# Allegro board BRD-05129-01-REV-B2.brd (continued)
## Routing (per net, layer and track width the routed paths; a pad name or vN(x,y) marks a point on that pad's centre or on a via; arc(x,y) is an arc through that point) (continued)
MIO47: length 73.6
  TOP w0.13: JA1.C34 14.33,62.75 v4(14.35,62.75) ; v1(54,81.78) 55.29,83.07 R554.1 R543.2 55.92,88.42 56.2,88.14 59.07,88.14 60.19,89.26 U98.30
  L05_SIG w0.102: v4(14.35,62.75) 13.88,62.28 13.88,61.96 14.19,61.64 14.58,61.64 14.87,61.35 16.07,61.35 16.19,61.23 17.18,61.23 17.43,60.98 18.54,60.98 19.81,59.71 23.16,59.71 23.88,60.43 24.42,60.43 24.6,60.61 24.6,60.96 24.72,61.08 25.08,61.08 25.21,60.96 25.21,60.61 25.38,60.43 25.64,60.43 25.81,60.61 25.81,61.04 25.99,61.22 26.25,61.22 26.42,61.04 26.42,60.61 26.6,60.43 26.86,60.43 27.03,60.61 27.03,61.04 27.21,61.22 27.47,61.22 27.64,61.04 27.64,60.61 27.82,60.43 28.07,60.43 28.25,60.61 28.25,61.04 28.43,61.22 28.68,61.22 28.86,61.04 28.86,60.61 29.04,60.43 29.29,60.43 29.47,60.61 29.47,61.04 29.65,61.22 29.9,61.22 30.08,61.04 30.08,60.61 30.26,60.43 30.51,60.43 30.69,60.61 30.69,61.04 30.87,61.22 31.12,61.22 31.3,61.04 31.3,60.61 31.48,60.43 31.73,60.43 31.91,60.61 31.91,61.04 32.09,61.22 32.92,61.22 46.38,74.68 46.38,76.91 47.14,77.67 50.21,77.67 54,81.46 v1(54,81.78)
MIO48: length 91
  TOP w0.13: U98.29 60.25,89.76 58.95,88.46 56.38,88.46 55.93,88.91 v1(55.93,89.31) R542.2 R553.1 ; JA1.C35 v4(13.46,62.79)
  L05_SIG w0.102: v4(13.46,62.79) 13.88,63.2 13.88,66.82 14.43,67.37 17.1,67.37 17.41,67.67 17.95,67.67 18.1,67.82 18.1,68.38 18.25,68.52 18.46,68.52 18.61,68.38 18.61,67.82 18.76,67.67 18.97,67.67 19.12,67.82 19.12,68.38 19.27,68.52 19.48,68.52 19.63,68.38 19.63,67.82 19.77,67.67 19.98,67.67 20.13,67.82 20.13,68.38 20.28,68.52 20.49,68.52 20.64,68.38 20.64,67.82 20.79,67.67 21,67.67 21.15,67.82 21.15,68.38 21.3,68.52 21.51,68.52 21.66,68.38 21.66,67.82 21.81,67.67 22.87,67.67 36.29,81.1 36.29,81.73 37.51,82.95 38.67,82.95 39.39,83.67 39.39,84.78 39.82,85.21 40.41,85.21 40.84,85.65 41.05,85.65 42.41,84.3 42.62,84.3 42.77,84.45 42.77,84.66 41.41,86.01 41.41,86.22 41.56,86.37 41.77,86.37 43.12,85.02 43.33,85.02 43.48,85.16 43.48,85.37 42.13,86.73 42.13,86.94 42.28,87.09 42.49,87.09 43.84,85.73 44.05,85.73 44.2,85.88 44.2,86.09 42.85,87.45 42.85,87.66 46.02,90.83 51.14,90.83 51.28,90.68 51.28,87.88 51.43,87.73 51.64,87.73 51.79,87.88 51.79,88.17 51.94,88.32 52.55,88.32 52.7,88.47 52.7,88.68 52.55,88.83 51.94,88.83 51.79,88.98 51.79,90.68 51.94,90.83 54.41,90.83 v1(55.93,89.31)
MIO49: length 93.9
  TOP w0.13: JA1.C36 v4(14.29,63.99) ; U98.35 63.53,87.77 63.24,87.47 63.24,85.69 R552.1 62.55,84.66 62.8,84.66 62.92,84.54 62.92,82.99 62.49,82.55 62.31,82.55 R541.2 61.97,79.92 v1(61.59,79.55)
  L05_SIG w0.102: v4(14.29,63.99) 14.77,63.51 14.77,61.99 15.14,61.62 16.11,61.62 16.26,61.47 19.09,61.47 19.66,60.9 22.65,60.9 23.54,61.79 31.62,61.79 32.67,62.84 32.67,63.05 32.08,63.65 32.08,63.86 32.23,64 32.44,64 33.03,63.41 33.24,63.41 33.39,63.56 33.39,63.77 32.8,64.36 32.8,64.57 32.95,64.72 33.16,64.72 33.75,64.13 33.96,64.13 34.11,64.28 34.11,64.49 33.52,65.08 33.52,65.29 33.67,65.44 33.88,65.44 34.47,64.85 34.68,64.85 34.83,65 34.83,65.21 34.24,65.8 34.24,66.01 34.38,66.16 34.6,66.16 35.19,65.57 35.4,65.57 35.55,65.72 35.55,65.93 34.95,66.52 34.95,66.73 35.1,66.88 35.31,66.88 35.91,66.29 36.12,66.29 36.27,66.43 36.27,66.65 35.67,67.24 35.67,67.45 35.82,67.6 36.03,67.6 36.62,67 36.83,67 36.98,67.15 36.98,67.36 36.39,67.96 36.39,68.17 36.54,68.32 36.75,68.32 37.34,67.72 37.55,67.72 37.7,67.87 37.7,68.08 37.11,68.67 37.11,68.88 37.26,69.03 37.47,69.03 38.06,68.44 38.27,68.44 38.42,68.59 38.42,68.8 37.83,69.39 37.83,69.6 37.98,69.75 38.19,69.75 38.78,69.16 38.99,69.16 39.14,69.31 39.14,69.52 38.55,70.11 38.55,70.32 38.7,70.47 38.91,70.47 39.5,69.88 39.71,69.88 39.86,70.03 39.86,70.24 39.27,70.83 39.27,71.04 39.41,71.19 39.62,71.19 40.22,70.6 40.43,70.6 43.4,73.57 43.4,73.9 44.35,74.85 44.7,74.85 45.61,75.76 45.61,76.85 46.92,78.15 49.12,78.15 50.21,79.24 50.72,79.24 55.51,84.03 57.11,84.03 v1(61.59,79.55)
MIO50: length 87.9
  TOP w0.13: JA1.B36 v4(16.01,64.02) ; U98.23 60.18,92.76 59.82,93.12 59.82,93.62 58.7,94.75 56.22,94.75 v1(55.93,95.04)
  L05_SIG w0.102: v1(55.93,95.04) 61.89,95.04 63.45,93.48 66.05,93.48 66.51,93.02 66.51,89.35 66.09,88.93 65.3,88.93 65.15,89.08 65.15,89.57 65,89.72 64.79,89.72 64.65,89.57 64.65,89.08 64.5,88.93 64.29,88.93 64.14,89.08 64.14,89.57 63.99,89.72 63.78,89.72 63.63,89.57 63.63,89.08 63.48,88.93 63.27,88.93 63.12,89.08 63.12,89.57 62.97,89.72 62.76,89.72 62.61,89.57 62.61,89.08 62.46,88.93 59.92,88.93 59.52,88.54 56.6,88.54 56.35,88.29 54.79,88.29 49.31,82.81 47.18,82.81 46.72,83.27 40.53,83.27 39.24,81.98 37.91,81.98 37.26,81.33 37.26,80 36.39,79.13 36.39,79.13 23.86,66.6 18.21,66.6 16.46,64.85 16.46,64.47 v4(16.01,64.02)
MIO51: length 92.3
  TOP w0.13: R536.2 55.16,96.84 v1(55.16,96.29) 55.16,95.04 55.85,94.35 58.21,94.35 58.66,93.91 58.66,93.23 59.63,92.26 U98.24 ; JA1.B37 v4(15.19,64.08)
  L05_SIG w0.102: v4(15.19,64.08) 15.59,64.49 15.59,64.89 16.38,65.68 16.38,66.73 16.74,67.09 23.66,67.09 36.78,80.2 36.78,81.53 37.71,82.46 39.04,82.46 40.33,83.75 42.07,83.75 46.92,83.75 47.38,83.29 49.11,83.29 54.6,88.78 56.15,88.78 57.06,89.69 57.16,89.69 57.31,89.84 57.31,92.6 57.46,92.75 57.67,92.75 57.82,92.6 57.82,89.84 57.96,89.69 59.69,89.69 59.84,89.84 59.84,92.98 59.98,93.13 60.2,93.13 60.34,92.98 60.34,89.84 60.49,89.69 60.72,89.69 61.23,90.2 61.23,93.4 60.19,94.44 55.58,94.44 55.16,94.86 v1(55.16,96.29)
MIO52: length 34.9
  TOP w0.13: JA1.D36 v4(13.47,64.02)
  L03_SIG w0.102: v1(41.17,74.24) 29.36,62.43 17.93,62.43 17.42,62.94 17.42,62.95 17.19,63.18 15.46,63.18 15.36,63.27 14.06,63.27 13.47,63.87 v4(13.47,64.02)
  BOTTOM w0.13: U37.1 v1(41.17,74.24)
MIO53: length 38.8
  TOP w0.13: JA1.D37 v4(12.65,64.08)
  L03_SIG w0.102: v4(12.65,64.08) 13.29,63.44 13.56,63.44 13.86,63.13 13.86,62 13.92,61.94 13.92,61.94 14.13,61.72 14.14,61.72 14.16,61.7 17.23,61.7 17.37,61.83 19.6,61.83 20.53,60.9 23.01,60.9 23.94,61.83 31.1,61.83 41,71.74 v1(41,72.25)
  BOTTOM w0.13: v1(41,72.25) 41.2,72.25 42.37,73.42 U37.31
MIO54: length 37
  TOP w0.13: JA1.D38 v4(12.65,64.72)
  L03_SIG w0.102: v1(38.48,77.21) 37.9,77.8 36.93,77.8 29.64,70.51 14.42,70.51 13.89,69.98 13.89,67.59 13.09,66.79 13.09,65.17 v4(12.65,64.72)
  BOTTOM w0.13: v1(38.48,77.21) U37.5
MIO55: length 35.6
  TOP w0.13: JA1.C38 v4(13.46,64.69)
  L03_SIG w0.102: v4(13.46,64.69) 13.83,64.33 13.83,63.86 14.14,63.55 15.47,63.55 15.64,63.38 17.46,63.38 17.88,62.97 28.85,62.97 v1(38.76,72.87)
  BOTTOM w0.13: v1(38.76,72.87) 38.76,74.67 39.8,75.71 U37.2
MIO56: length 31.8
  TOP w0.13: JA1.C39 v4(14.29,65.9)
  L03_SIG w0.102: v1(38.48,76.21) 37.93,76.21 30.28,68.57 18.96,68.57 17.6,67.2 15.16,67.2 14.78,66.82 14.78,66.39 v4(14.29,65.9)
  BOTTOM w0.13: U37.3 v1(38.48,76.21)
MIO57: length 31.8
  TOP w0.13: JA1.C40 v4(14.29,66.53)
  L03_SIG w0.102: v1(39.29,76.71) 37.57,76.71 29.94,69.08 18.74,69.08 17.06,67.41 14.7,67.41 14.29,66.99 v4(14.29,66.53)
  BOTTOM w0.13: U37.4 v1(39.29,76.71)
MIO58: length 40.2
  TOP w0.13: JA1.B40 v4(15.19,65.99)
  L03_SIG w0.102: v1(42.34,71.73) 42.34,72.94 42.4,73.01 42.4,73.93 41.56,74.77 40.87,74.77 39.77,73.68 38.83,73.68 29.41,64.26 17.73,64.26 17.08,63.61 15.81,63.61 15.59,63.83 15.59,65.58 v4(15.19,65.99)
  BOTTOM w0.13: U37.29 43.37,73.73 43.36,73.72 43.36,73.49 43.09,73.21 42.98,73.21 42.34,72.57 v1(42.34,71.73)
MIO59: length 32.1
  TOP w0.13: JA1.B41 v4(15.19,66.62)
  L03_SIG w0.102: v1(39.67,77.71) 39.85,77.54 39.85,76.45 39.06,75.66 38.06,75.66 30.36,67.96 19.32,67.96 18.17,66.81 17.51,66.81 17.34,66.98 15.54,66.98 v4(15.19,66.62)
  BOTTOM w0.13: U37.6 v1(39.67,77.71)
MIO60: length 30.6
  TOP w0.13: JA1.B42 v4(16.01,67.83)
  L03_SIG w0.102: v4(16.01,67.83) 16.38,68.2 16.38,69.19 16.86,69.67 29.64,69.67 v1(37.18,77.21)
  BOTTOM w0.13: v1(37.18,77.21) 38.18,78.21 U37.7
MIO61: length 37
  TOP w0.13: JA1.A38 v4(16,64.69)
  L03_SIG w0.102: v1(40.84,80.18) 41.88,79.14 41.88,76.32 39.79,74.23 38.7,74.23 29.52,65.05 16.35,65.05 v4(16,64.69)
  BOTTOM w0.13: U37.9 41.87,79.61 41.3,80.18 v1(40.84,80.18)
MIO62: length 36.8
  TOP w0.13: JA1.A39 v4(16.83,65.9)
  L03_SIG w0.102: v7(41.83,80.36) 41.42,80.77 40.61,80.77 40.28,80.44 40.28,79.75 41.09,78.94 41.09,76.33 39.53,74.77 38.53,74.77 29.29,65.53 17.2,65.53 v4(16.83,65.9)
  BOTTOM w0.13: v7(41.83,80.36) 42.37,79.82 U37.10
MIO63: length 39.8
  TOP w0.13: JA1.A40 v4(16.83,66.53)
  L03_SIG w0.102: v1(43.76,80.31) 42.47,81.6 39.65,81.6 39.37,81.32 39.37,78.73 40.39,77.71 40.39,76.32 39.33,75.25 38.33,75.25 30.42,67.34 20.27,67.34 19.02,66.09 17.27,66.09 v4(16.83,66.53)
  BOTTOM w0.13: U37.13 43.87,80.2 v1(43.76,80.31)
MIO64_NC: length 0.4
  TOP w0.13: JA1.D40 v4(12.65,65.99)
MIO65_NC: length 0.4
  TOP w0.13: JA1.D41 v4(12.65,66.62)
MIO66: length 126.6
  TOP w0.13: U94.B4 U94.A4 107.02,103.54 106.51,104.05 v1(106.13,104.05) ; JA1.D42 v4(13.47,67.83)
  L05_SIG w0.102: v4(13.47,67.83) 13.06,68.24 13.06,68.72 11.91,69.88 11.91,72.36 12.65,73.1 23.99,73.1 30.77,79.88 30.77,81.75 31.12,82.1 31.12,84.59 35.81,89.28 39.58,89.28 42.22,91.91 42.22,92.11 44.55,94.43 46.68,94.43 48.61,96.36 48.61,97 49.37,97.76 51.79,97.76 54.3,100.27 62.85,100.27 63.72,101.15 78.03,101.15 86.31,109.43 104.74,109.43 106.74,107.43 106.74,104.66 v1(106.13,104.05)
MIO67: length 124.3
  TOP w0.13: JA1.C42 v4(14.29,67.8) ; v1(106,107.35) U94.A1 108.65,107.35 109.04,106.96 U94.B1
  L05_SIG w0.102: v4(14.29,67.8) 13.87,68.22 13.87,70.08 13.58,70.36 12.59,70.36 12.47,70.49 12.47,71.67 12.59,71.8 17.04,71.8 17.52,72.28 23.86,72.28 32.13,80.56 32.13,83.97 36.93,88.77 40.38,88.77 45.41,93.8 47.19,93.8 49.58,96.19 50.97,96.19 54.56,99.77 63.41,99.77 64.31,100.67 74.25,100.67 74.39,100.52 74.39,100.32 74.54,100.17 74.75,100.17 74.9,100.32 74.9,100.52 75.05,100.67 75.26,100.67 75.41,100.52 75.41,100.32 75.56,100.17 75.77,100.17 75.92,100.32 75.92,100.52 76.07,100.67 76.28,100.67 76.43,100.52 76.43,100.32 76.57,100.17 76.79,100.17 76.93,100.32 76.93,100.52 77.08,100.67 78.55,100.67 86.82,108.95 103.03,108.95 104.63,107.35 v1(106,107.35)
MIO68: length 130.3
  TOP w0.13: JA1.C43 v4(14.29,68.44) ; U94.B8 111.82,100.12 112.21,99.73 U94.A8 v1(114.69,99.73)
  L05_SIG w0.102: v1(114.69,99.73) 112.78,101.65 105.58,101.65 104.26,102.97 104.26,105.88 101.68,108.46 87.7,108.46 78.59,99.36 54.86,99.36 51.16,95.66 49.56,95.66 47.11,93.21 45.64,93.21 40.59,88.16 37.23,88.16 33.99,84.92 33.99,83.85 32.71,82.57 32.71,80.46 23.7,71.45 18.21,71.45 17.4,70.63 16.73,70.63 16.53,70.43 15.06,70.43 14.73,70.1 14.73,68.88 v4(14.29,68.44)
MIO69_NC: length 0.6
  TOP w0.13: JA1.C44 v4(13.46,68.5)
MIO70: length 125.9
  TOP w0.13: v1(116.09,89.69) 118.23,89.69 119.09,90.56 U95.4 ; JA1.B44 v4(15.19,68.53)
  L05_SIG w0.102: v1(116.09,89.69) 114.22,89.69 113.96,89.96 110.89,89.96 109.45,91.4 107.92,91.4 105.61,93.71 105,93.71 104.82,93.53 104.82,93.1 104.7,92.98 104.34,92.98 104.21,93.1 104.21,93.53 104.03,93.71 91.32,93.71 90.55,94.47 79.34,94.47 79.03,94.78 69.58,94.78 69.24,94.43 63.88,94.43 61.51,96.8 54.81,96.8 53.72,95.7 53.72,94.69 52.96,93.92 52.96,93.09 51.18,91.31 45.82,91.31 40.56,86.05 39.72,86.05 38.32,84.65 38.32,83.81 37.94,83.43 37.31,83.43 35.81,81.93 35.81,81.3 23.8,69.29 17.88,69.29 17.7,69.47 16.66,69.47 16.3,69.11 15.77,69.11 v4(15.19,68.53)
  BOTTOM w0.13: v1(116.09,89.69) 116.13,89.73 R683.2
MIO71: length 133.5
  TOP w0.13: R682.1 v1(121.88,94.46) 121.63,94.22 U95.2 ; JA1.B45 v4(16.01,69.73)
  L05_SIG w0.102: v1(121.88,94.46) 119.66,96.68 115.5,96.68 113.86,98.32 106.7,98.32 100.2,104.82 100.2,106.73 98.94,107.98 87.97,107.98 77.88,97.89 54.07,97.89 51.32,95.13 51.32,94.7 49.09,92.48 45.61,92.48 40.48,87.35 37.82,87.35 35.54,85.07 35.54,84.23 33.19,81.88 33.19,80.26 23.23,70.3 17.7,70.3 17.55,70.45 16.81,70.45 16.6,70.24 16.52,70.24 v4(16.01,69.73)
MIO72: length 127.2
  TOP w0.13: JA1.B46 v4(15.19,69.8) ; v1(116.06,90.85) 116.51,91.31 117.39,91.31 117.82,91.74 U95.5 117.82,93.82 118.03,94.02 120.2,94.02 120.36,93.86 U95.3
  L05_SIG w0.102: v1(116.06,90.85) 113.79,93.12 113.58,93.12 113.32,92.85 113.11,92.85 112.96,93 112.96,93.21 113.22,93.48 113.22,93.69 112.72,94.19 91.53,94.19 90.76,94.97 82.93,94.97 82.92,94.95 79.54,94.95 79.23,95.26 71.59,95.26 69.57,97.28 54.35,97.28 52.02,94.94 52.02,94 51.61,93.59 51.61,93.06 50.44,91.89 45.74,91.89 45.64,91.79 45.62,91.79 40.46,86.64 39.16,86.64 34.25,81.72 34.25,80.42 23.6,69.77 17.9,69.77 17.83,69.7 16.57,69.7 16.2,69.33 15.66,69.33 v4(15.19,69.8)
  BOTTOM w0.13: R681.1 115.8,90.59 v1(116.06,90.85)
MIO73_NC: length 0.4
  TOP w0.13: JA1.A42 v4(16.83,67.8)
MIO74_NC: length 0.4
  TOP w0.13: JA1.A43 v4(16.83,68.44)
MIO75_NC: length 0.6
  TOP w0.13: JA1.A44 v4(16,68.5)
MIO76: length 60.7
  TOP w0.13: JA1.D44 v4(12.65,68.53)
  L03_SIG w0.102: v1(7.62,68.7) 7.79,68.53 v4(12.65,68.53)
  L05_SIG w0.102: v1(7.62,68.7) 7.62,68.11 7.62,62.71 7.92,62.4 7.92,61.49 7.57,61.13 7.57,58.42 8.56,57.43 9.65,57.43 10.05,57.02 10.05,54.98 10.65,54.38 10.65,50.91 11.98,49.58 11.98,45.9 13.34,44.55 17.53,44.55 17.7,44.73 23.28,44.73 26.23,41.79 31.8,41.79 33.11,40.48 33.57,40.48 34.48,39.57 34.48,38.24 v1(34.99,37.73)
  BOTTOM w0.13: U19.4 34.29,38.72 34.99,38.02 v1(34.99,37.73)
MIO77: length 55.9
  TOP w0.13: JA1.D45 v4(13.47,69.73)
  L03_SIG w0.102: v1(7.67,70.07) 8.48,69.26 13,69.26 v4(13.47,69.73)
  L05_SIG w0.102: v1(7.67,70.07) 8.73,69.01 8.73,63.62 9.57,62.78 9.57,59.49 10.21,58.85 10.21,57.71 10.54,57.38 10.54,55.18 11.13,54.58 11.13,51.35 12.43,50.06 13.76,50.06 14.17,49.65 14.17,48.33 14.68,47.82 14.68,46.68 15.27,46.08 17.23,46.08 17.88,45.44 24.2,45.44 24.78,44.86 34.4,44.86 v1(34.69,44.57)
  BOTTOM w0.13: U19.22 v1(34.69,44.57)
MODE0_C2M: length 3.6
  TOP w0.13: JA1.A27 v4(16.83,58.28)
  BOTTOM w0.13: R165.1 19.17,57.7 19.05,57.58 TP65.1 17.53,57.58 v4(16.83,58.28)
MODE1_C2M: length 3.3
  TOP w0.13: JA1.A28 v4(16.83,58.91)
  BOTTOM w0.13: v4(16.83,58.91) TP64.1 19.16,58.91 19.22,58.97 R164.1
MODE2_C2M: length 4.8
  TOP w0.13: JA1.A29 v4(16,58.98)
  BOTTOM w0.13: v4(16,58.98) 16.63,59.61 17.32,59.61 17.95,60.24 TP63.1 R163.1
MODE3_C2M: length 3.8
  TOP w0.13: JA1.A30 v4(16.83,60.18)
  BOTTOM w0.13: R162.1 TP62.1 18.16,61.51 v4(16.83,60.18)
MOTOR_CS_B_R: length 6.2
  TOP w0.13: v1(51.74,52.27) R756.2 ; v1(51.74,52.27) R760.2 ; v1(51.74,52.27) R758.2
  BOTTOM w0.13: v1(51.74,52.27) 51.46,52.55 U109.7
MOTOR_PA_CRNT: length 49.2
  TOP w0.381: v1(84.88,54.43) 85.29,54.02 86.23,54.02 86.62,54.41 87.31,54.41 87.8,54.91 J52.1
  L12_SIG w0.381: v1(84.88,54.43) 88.13,51.18 90.88,51.18 94.48,47.57 94.48,44.52 97.43,41.58 98.73,41.58 101.01,39.29 118.91,39.29 v1(119.41,38.78)
  BOTTOM w0.381: v1(119.41,38.78) C723.1 119.41,37.02 R646.2 ; v1(84.88,54.43) R61.1
MOTOR_PA_CS_B: length 10
  TOP w0.13: v1(56.65,42.96) 55.16,44.45 55.16,48.85 R756.1
  BOTTOM w0.13: U108.10 v1(56.65,42.96)
MOTOR_PA_CURRENT+: length 2.6
  TOP w0.381: C813.1 v1(64.88,41.82)
  BOTTOM w0.254: U108.8 64.39,42.31 v1(64.88,41.82)
  BOTTOM w0.381: C813.1 v1(64.88,41.82)
MOTOR_PA_CURRENT-: length 2.4
  TOP w0.381: C812.1 v1(64.88,42.96)
  BOTTOM w0.254: U108.7 v1(64.88,42.96)
  BOTTOM w0.381: C812.1 v1(64.88,42.96)
MOTOR_PA_DATAA: length 10.8
  BOTTOM w0.13: U108.14 55.98,45.56 53.79,47.75 53.79,48.99 51.43,51.35 51.43,51.84 51.11,52.15 U109.8
MOTOR_PA_DATAB: length 11.5
  BOTTOM w0.13: U108.13 55.74,44.91 53.03,47.62 53.03,48.79 50.31,51.51 U109.9
MOTOR_PA_HS: length 10.6
  TOP w0.254: U102.4 107.1,33.97 107.23,33.84 107.23,33.3 107.1,33.17 C688.2
  TOP w0.381: v1(122.01,39.9) 122.01,41.56 R638.1 ; v3(108.99,36.58) 108.2,35.78 108.2,33.45 107.48,32.73 C688.2
  BOTTOM w0.381: U105.8 v1(122.01,39.9)
  vias: v3(109.68,37.29) v3(110.14,36.58) v3(110.82,37.29) v3(110.82,35.89) v3(111.28,36.58) v3(111.97,37.29) v3(111.97,35.89) v3(112.42,36.58) v3(113.11,37.29) v3(113.11,35.89) v3(113.57,36.58) v3(114.25,37.29) v3(114.25,35.89) v3(115.08,39.31) v3(115.08,38.3) v3(115.08,37.28) v3(115.08,36.27) v3(116.23,39.31) v3(116.23,38.3) v3(116.23,37.28) v3(116.23,36.27) v3(117.37,39.31) v3(117.37,38.3) v3(117.37,37.28) v3(117.37,36.27) v3(118.39,39.31) v3(118.39,38.3) v3(118.39,37.28)
MOTOR_PA_I: length 1.8
  BOTTOM w0.381: R646.1 120.91,37 121.08,37.17 U105.5
MOTOR_PA_OUT: length 5.4
  TOP w0.381: R638.2 124.61,41.31 v1(124.61,39.92)
  BOTTOM w0.381: v1(128.25,44.95) 127.69,44.95 127.31,45.34 R641.1 ; U105.1 v1(124.61,39.92)
  vias: v3(128.25,46.22) v3(128.25,43.94) v3(128.25,42.92) v3(128.25,42.03) v3(128.25,41.02) v3(128.25,40) v3(129.39,46.22) v3(129.39,44.95) v3(129.39,43.94) v3(129.39,42.92) v3(129.39,42.03) v3(129.39,41.02) v3(129.39,40) v3(130.41,42.03) v3(130.41,41.02) v3(130.41,40) v3(131.43,42.03) v3(131.43,41.02) v3(131.43,40) v3(132.44,42.03) v3(132.44,41.02) v3(132.44,40)
MOTOR_PA_R_V+: length 13.3
  L12_SIG w0.254: v1(67.25,47.35) 67.49,47.11 72.07,47.11 73.33,48.37 73.33,51.1 v1(73.11,51.32)
  BOTTOM w0.254: U127.4 R702.2 73.62,50.81 v1(73.11,51.32) ; R738.1 v1(67.25,47.35)
MOTOR_PA_R_V-: length 15.7
  L12_SIG w0.254: v1(73.11,52.46) 73.96,51.61 73.96,48.1 72.34,46.48 67.51,46.48 v1(67.25,46.21)
  BOTTOM w0.254: U127.5 R703.2 73.62,52.97 v1(73.11,52.46) ; R739.1 v1(67.25,46.21)
MOTOR_PA_SCLK: length 10.8
  BOTTOM w0.13: U108.15 56.31,46.21 55.14,47.38 55.14,49.58 54.95,49.77 54.37,49.77 54.18,49.96 54.18,50.23 54.37,50.41 54.95,50.41 55.14,50.6 55.14,51.62 54.98,51.77 54.14,51.77 R755.1
MOTOR_PA_VOCM: length 76.5
  TOP w0.381: C711.1 125.67,37.57 v1(125.82,37.42)
  L05_SIG w0.381: v1(125.82,37.42) 125.08,37.42 123.72,38.78 v1(122.98,38.78) 118.46,34.26 110.99,34.26 110.36,34.9 107.34,34.9 105.33,36.9 97.94,36.9 91.31,43.53 91.31,46.63 90.42,47.52 85.68,47.52 v1(83.34,49.86) 82.15,48.66 77,48.66 v1(76.11,49.55) 74.02,47.47 72.01,47.47 v1(71.31,48.16) v1(70.17,48.16)
  BOTTOM w0.254: U128.2 83.48,49.99 v1(83.34,49.86) ; U127.2 76.24,49.69 v1(76.11,49.55)
  BOTTOM w0.381: U105.3 125.42,37.82 v1(125.82,37.42) ; U123.7 71.08,48.39 v1(71.31,48.16) ; U123.6 70.43,48.43 v1(70.17,48.16) ; U105.7 122.67,38.47 v1(122.98,38.78)
MOTOR_PA_VOCM2: length 17.9
  L10_SIG w0.381: v1(71.39,45.51) v1(72.54,45.51) 73.39,45.51 v1(77.64,49.76) 78.67,50.8 84.16,50.8 v1(84.88,50.07)
  BOTTOM w0.381: v1(84.88,50.07) R58.1 ; v1(77.64,49.76) R63.1
MOTOR_PA_VOLT: length 54.9
  L12_SIG w0.381: v1(122.15,45.03) 122.15,44.81 120.95,43.61 114.73,43.61 112.29,46.05 111.2,46.05 108.15,49.09 102.56,49.09 101.4,50.25 99.48,50.25 97.92,51.81 95.22,51.81 90.5,56.54 80.87,56.54 78.3,53.97 v1(77.64,53.97)
  BOTTOM w0.381: v1(77.64,53.97) R64.1 ; v1(122.15,45.03) U135.1 U135.2
MOTOR_PA_VOLTAGE+: length 2.6
  TOP w0.381: C811.1 v1(64.88,47.35)
  BOTTOM w0.254: v1(64.88,47.35) 64.39,46.86 U108.1
  BOTTOM w0.381: C811.1 v1(64.88,47.35)
MOTOR_PA_VOLTAGE-: length 2.4
  TOP w0.381: C810.1 v1(64.88,46.21)
  BOTTOM w0.254: U108.2 v1(64.88,46.21)
  BOTTOM w0.381: C810.1 v1(64.88,46.21)
MOTOR_PB_CRNT: length 49.6
  TOP w0.381: v1(84.88,63.22) 85.32,62.78 87.32,62.78 87.8,63.27 J53.1
  L12_SIG w0.381: v1(119,47.85) 119,47.87 119.81,48.69 119.81,50.59 119.3,51.1 110.56,51.1 109.77,51.89 107.79,51.89 105.71,53.97 98.57,53.97 97.49,55.05 95.46,55.05 91.61,58.9 89.2,58.9 v1(84.88,63.22)
  BOTTOM w0.381: R650.2 C734.1 119.01,47.87 v1(119,47.85) ; v1(84.88,63.22) R712.1
MOTOR_PB_CS_B: length 10
  TOP w0.13: v1(56.64,51.13) 55.52,51.13 55.27,51.37 55.27,55.01 55.14,55.15 54.79,55.15 54.65,55.01 54.65,52.54 R758.1
  BOTTOM w0.13: U110.10 v1(56.64,51.13)
MOTOR_PB_CURRENT+: length 2.6
  TOP w0.381: C817.1 v1(64.88,49.99)
  BOTTOM w0.254: v1(64.88,49.99) 64.39,50.48 U110.8
  BOTTOM w0.381: C817.1 v1(64.88,49.99)
MOTOR_PB_CURRENT-: length 2.4
  TOP w0.381: C816.1 v1(64.88,51.13)
  BOTTOM w0.254: U110.7 v1(64.88,51.13)
  BOTTOM w0.381: C816.1 v1(64.88,51.13)
MOTOR_PB_DATAA: length 12.1
  L05_SIG w0.102: v1(52.35,48.36) 52.35,50.92 55.15,53.73 v1(56.68,53.73)
  BOTTOM w0.13: U111.6 50.9,46.88 52.12,46.88 52.35,47.11 v1(52.35,48.36) ; U110.14 v1(56.68,53.73)
MOTOR_PB_DATAB: length 11.8
  L05_SIG w0.102: v1(56,53.08) 54.43,51.5 54.43,48.06 v1(52.86,46.49)
  BOTTOM w0.13: U110.13 v1(56,53.08) ; U111.7 v1(52.86,46.49)
MOTOR_PB_HS: length 10.8
  TOP w0.254: C696.2 107.1,50.06 107.23,50.19 107.23,50.73 107.1,50.87 U103.4
  TOP w0.381: v1(122.65,49.91) 122.65,51.09 R639.1 ; C696.2 107.44,49.62 108.17,50.36 108.17,52.65 v3(108.99,53.47)
  BOTTOM w0.381: U106.8 v1(122.65,49.91)
  vias: v3(109.68,54.18) v3(110.14,53.47) v3(110.82,54.18) v3(110.82,52.78) v3(111.28,53.47) v3(111.97,54.18) v3(111.97,52.78) v3(112.42,53.47) v3(113.11,54.18) v3(113.11,52.78) v3(113.57,53.47) v3(114.25,54.18) v3(114.25,52.78) v3(115.19,51.99) v3(115.19,50.97) v3(115.19,49.96) v3(116.33,51.99) v3(116.33,50.97) v3(116.33,49.96) v3(117.47,51.99) v3(117.47,50.97) v3(117.47,49.96) v3(118.36,54.91) v3(118.36,53.89) v3(118.36,52.88) v3(118.36,51.99) v3(118.36,50.97) v3(118.36,49.96) v3(119.25,54.91) v3(119.25,53.89) v3(119.25,52.88) v3(119.25,51.99) v3(119.25,50.97) v3(119.25,49.96)
MOTOR_PB_I: length 2
  BOTTOM w0.381: U106.5 121.93,47.2 121.69,46.97 R650.1
MOTOR_PB_OUT: length 14.6
  TOP w0.381: R639.2 125.25,51.85 v1(125.25,49.88)
  BOTTOM w0.381: v1(128.32,53.89) 119.88,53.89 R647.1 ; U106.1 v1(125.25,49.88)
  vias: v3(128.32,52.88) v3(128.32,51.86) v3(128.32,50.97) v3(128.32,49.96) v3(128.32,48.94) v3(129.59,53.89) v3(129.59,52.88) v3(129.59,51.86) v3(129.59,50.97) v3(129.59,49.96) v3(129.59,48.94) v3(136.83,53.77) v3(136.83,52.75) v3(136.83,51.74) v3(136.83,50.85) v3(136.83,49.83) v3(136.83,48.81)
MOTOR_PB_SCLK: length 10.8
  BOTTOM w0.13: U110.15 55.64,54.38 55.32,54.7 55.32,57.43 55.17,57.57 54.56,57.57 54.42,57.43 R757.1
MOTOR_PB_VOCM: length 71.4
  L05_SIG w0.381: v1(70.17,56.04) v1(71.31,56.04) 72.47,57.2 74.8,57.2 v1(76.11,58.5) 77.33,57.27 81.81,57.27 v1(83.34,58.8) 85.59,56.56 90.52,56.56 95.32,51.76 99.79,51.76 102.51,49.04 112.04,49.04 113.58,50.59 119.45,50.59 v1(121.54,48.5) 122.3,48.5 123.14,47.67 v1(126.23,47.67)
  BOTTOM w0.254: U130.2 83.48,58.94 v1(83.34,58.8) ; U129.2 76.24,58.63 v1(76.11,58.5)
  BOTTOM w0.381: v1(71.31,56.04) 71.08,56.27 U124.7 ; U124.6 70.43,56.3 v1(70.17,56.04) ; U106.3 126.05,47.85 v1(126.23,47.67) 126.43,47.48 C713.1 ; U106.7 v1(121.54,48.5)
MOTOR_PB_VOCM2: length 18.4
  L10_SIG w0.381: v1(84.88,59.02) 83.88,58.01 81.86,58.01 81.16,58.71 v1(77.64,58.71) 74.35,55.41 74.35,55.2 v1(72.54,53.39) v1(71.39,53.39)
  BOTTOM w0.381: v1(77.64,58.71) R707.1 ; v1(84.88,59.02) R711.1
MOTOR_PB_VOLT: length 62.6
  L12_SIG w0.381: v1(124.69,64.77) 124.69,64.66 120.72,60.69 120.72,57.32 119.88,56.49 99.67,56.49 98.02,58.14 96.24,58.14 91.66,62.71 89.05,62.71 86.15,65.6 81.73,65.6 79.05,62.92 v1(77.64,62.92)
  BOTTOM w0.381: v1(124.69,64.77) 124.69,62.65 124.39,62.35 U136.7 U136.6 ; v1(77.64,62.92) R708.1
MOTOR_PB_VOLTAGE+: length 2.6
  TOP w0.381: C815.1 v1(64.88,55.52)
  BOTTOM w0.254: U110.1 64.39,55.03 v1(64.88,55.52)
  BOTTOM w0.381: C815.1 v1(64.88,55.52)
MOTOR_PB_VOLTAGE-: length 2.4
  TOP w0.381: C814.1 v1(64.88,54.38)
  BOTTOM w0.254: U110.2 v1(64.88,54.38)
  BOTTOM w0.381: C814.1 v1(64.88,54.38)
MOTOR_PC_CRNT: length 49.6
  TOP w0.381: J54.1 87.42,71.67 85.39,71.67 84.88,72.18 v1(84.88,72.51)
  L12_SIG w0.381: v1(84.88,72.51) 84.88,72.17 88.3,68.74 88.3,67.09 90.22,65.17 98.45,65.17 99.49,66.21 110.54,66.21 113.2,63.55 116.25,63.55 119.1,60.69 v1(119.1,58.34)
  BOTTOM w0.381: v1(84.88,72.51) R720.1 ; v1(119.1,58.34) C743.1 R656.2
MOTOR_PC_CS_B: length 10
  TOP w0.13: v1(56.53,59.3) 53.61,59.3 53.01,58.69 53.01,54.75 R760.1
  BOTTOM w0.13: U112.10 v1(56.53,59.3)
MOTOR_PC_CURRENT+: length 2.6
  TOP w0.381: C821.1 v1(64.88,58.15)
  BOTTOM w0.254: U112.8 64.39,58.65 v1(64.88,58.15)
  BOTTOM w0.381: C821.1 v1(64.88,58.15)
MOTOR_PC_CURRENT-: length 2.4
  TOP w0.381: C820.1 v1(64.88,59.3)
  BOTTOM w0.254: U112.7 v1(64.88,59.3)
  BOTTOM w0.381: C820.1 v1(64.88,59.3)
MOTOR_PC_DATAA: length 19.9
  L12_SIG w0.102: v1(56.63,61.6) 55.14,60.1 55.14,58.62 55.11,58.6 55.11,49.52 v1(51.61,46.02)
  BOTTOM w0.13: v1(56.63,61.6) 56.94,61.9 U112.14 ; U111.8 51.53,46.09 v1(51.61,46.02)
MOTOR_PC_DATAB: length 22.2
  L12_SIG w0.102: v1(55.62,61.6) 54.52,60.5 54.52,49.62 50.81,45.91 v1(50.81,45.07)
  BOTTOM w0.13: v1(55.62,61.6) 56.11,61.1 57.82,61.1 U112.13 ; U111.9 50.31,45.69 50.81,45.19 v1(50.81,45.07)
MOTOR_PC_HS: length 10.8
  TOP w0.254: C703.2 106.59,66.95 106.73,67.09 106.73,67.62 106.59,67.76 U104.4
  TOP w0.381: C703.2 107.18,66.51 107.41,66.75 107.41,67.23 107.69,67.51 107.69,69.57 v3(108.49,70.36) ; R640.1 122.65,60.11 v1(122.65,58.97)
  BOTTOM w0.381: U107.8 v1(122.65,58.97)
  vias: v3(109.17,71.07) v3(109.63,70.36) v3(110.31,71.07) v3(110.31,69.67) v3(110.77,70.36) v3(111.46,71.07) v3(111.46,69.67) v3(111.91,70.36) v3(112.6,71.07) v3(112.6,69.67) v3(113.06,70.36) v3(113.74,71.07) v3(113.74,69.67) v3(114.93,68.37) v3(114.93,62.28) v3(114.93,61.26) v3(114.93,60.24) v3(115.95,68.37) v3(115.95,62.28) v3(115.95,61.26) v3(115.95,60.24) v3(116.96,68.37) v3(116.96,62.28) v3(116.96,61.26) v3(116.96,60.24) v3(117.98,68.37) v3(117.98,67.36) v3(117.98,64.31) v3(117.98,63.29) v3(117.98,62.28) v3(117.98,61.26) v3(117.98,60.24) v3(120.16,67.32)
MOTOR_PC_I: length 3
  BOTTOM w0.381: U107.5 122.26,56.35 121.84,55.93 120.95,55.93 120.44,56.43 R656.1
MOTOR_PC_OUT: length 5.6
  TOP w0.381: R640.2 125.25,60.87 v1(125.25,58.95)
  BOTTOM w0.381: R651.1 133.24,62.6 v1(132.35,61.71) ; U107.1 v1(125.25,58.95)
  vias: v3(128.03,60.7) v3(128.03,59.68) v3(128.03,58.67) v3(128.03,57.65) v3(128.03,56.63) v3(129.3,60.7) v3(129.3,59.68) v3(129.3,58.67) v3(129.3,57.65) v3(129.3,56.63) v3(130.32,60.7) v3(130.32,59.68) v3(131.34,62.73) v3(131.34,61.71) v3(131.34,60.7) v3(131.34,59.68) v3(132.35,62.73) v3(132.35,60.7) v3(132.35,59.68)
MOTOR_PC_SCLK: length 10.8
  BOTTOM w0.13: R759.1 53.64,60.78 55.4,62.55 U112.15
MOTOR_PC_VOCM: length 71.8
  L05_SIG w0.381: v1(126.23,56.94) 122.48,56.94 v1(121.64,57.78) 121,57.78 119.38,56.16 101.16,56.16 99.23,58.09 96.34,58.09 91.72,62.71 89,62.71 83.96,67.75 v1(83.34,67.75) 82.24,66.65 76.9,66.65 v1(76.11,67.44) 73.45,64.79 72.08,64.79 71.31,64.02 v1(71.31,63.46) v1(70.17,63.46)
  BOTTOM w0.254: v1(76.11,67.44) 76.24,67.58 U131.2 ; v1(83.34,67.75) 83.48,67.89 U132.2
  BOTTOM w0.381: v1(71.31,63.46) 71.08,63.69 U125.7 ; U125.6 70.43,63.72 v1(70.17,63.46) ; U107.3 126.18,57 v1(126.23,56.94) 126.3,57.01 C715.1 ; v1(121.64,57.78) 121.77,57.65 U107.7
MOTOR_PC_VOCM2: length 20.2
  L10_SIG w0.381: v1(84.88,67.96) 83.59,66.67 78.63,66.67 v1(77.64,67.66) 72.93,62.95 72.93,61.21 v1(72.54,60.81) v1(71.39,60.81)
  BOTTOM w0.381: v1(84.88,67.96) R719.1 ; v1(77.64,67.66) R715.1
MOTOR_PC_VOLT: length 57.3
  L10_SIG w0.381: v1(77.64,71.86) 78.03,71.47 79.5,71.47 79.8,71.78 81.81,71.78 82.11,71.47 85.59,71.47 88.29,68.78 88.29,67.1 90.22,65.17 98.24,65.17 99.34,66.26 125.4,66.26 125.96,65.7 v1(125.96,64.82)
  BOTTOM w0.381: v1(125.96,64.82) U136.1 U136.2 ; v1(77.64,71.86) R716.1
MOTOR_PC_VOLTAGE+: length 2.6
  TOP w0.381: C819.1 v1(64.88,63.69)
  BOTTOM w0.254: v1(64.88,63.69) 64.39,63.2 U112.1
  BOTTOM w0.381: C819.1 v1(64.88,63.69)
MOTOR_PC_VOLTAGE-: length 2.4
  TOP w0.381: C818.1 v1(64.88,62.55)
  BOTTOM w0.254: U112.2 v1(64.88,62.55)
  BOTTOM w0.381: C818.1 v1(64.88,62.55)
MOTOR_SCLK_R: length 6.3
  BOTTOM w0.13: R759.2 v1(51.74,53.16) ; v1(51.74,53.16) 51.54,52.95 U109.6 ; v1(51.74,53.16) R757.2 ; v1(51.74,53.16) R755.2
MP5016_DVDT: length 3.4
  TOP w0.13: U41.10 16.9,93.4 v1(17.16,93.14)
  BOTTOM w0.13: v1(17.16,93.14) 17.16,93.57 17,93.74 C206.1
MP5016_EN: length 2.5
  TOP w0.13: v1(16.28,93.65) 16.28,94.33 16.4,94.46 U41.9
  BOTTOM w0.13: v1(16.28,93.65) 16.18,93.74 R133.2
MP5016_GATE: length 4.1
  TOP w0.127: U41.8 15.9,94.39 v1(15.29,93.77)
  TOP w0.13: U41.8 14.32,95 Q5.3
  BOTTOM w0.13: C234.1 v1(15.29,93.77)
MP5016_ILIMIT: length 1.5
  TOP w0.13: R135.1 U41.4
MP5016_MODE: length 2.4
  TOP w0.13: U41.5 15.9,97.42 v6(15.51,97.8) 15.51,98.44 C235.1
  BOTTOM w0.13: R134.1 v6(15.51,97.8)
OSC_25M_CLK: length 2
  BOTTOM w0.13: U91.1 70.6,79.68 70.08,79.17 R501.2
OSC_25M_CLK_R: length 1.9
  BOTTOM w0.13: U92.3 67.81,79.09 67.88,79.16 R501.1
OSC_25M_OE: length 1.6
  BOTTOM w0.13: U92.1 63.97,80.69 63.97,80.69 R500.2
OSC_26M_OE: length 2.1
  BOTTOM w0.13: U89.1 1.85,64.86 R494.2
PA_HB: length 3.5
  TOP w0.254: C688.1 106.2,33.11 106.03,33.28 106.03,33.89 106.1,33.95 U102.2
  TOP w0.381: C688.1 104.88,32.73
PA_HO: length 1.2
  TOP w0.254: U102.3 v1(106.6,33.59)
PA_HOG: length 1.2
  TOP w0.381: Q35.4 v1(109.22,33.48)
PA_RDT: length 2.6
  TOP w0.254: R625.1 107.74,41.1 107.99,40.85 107.99,40.3 107.6,39.91 U102.6
PB_HB: length 3.8
  TOP w0.254: U103.2 106.1,50.84 106.03,50.78 106.03,50.17 106.2,50 C696.1
  TOP w0.381: C696.1 104.6,49.62
PB_HO: length 1.2
  TOP w0.254: U103.3 v1(106.6,50.48)
PB_HOG: length 1.2
  TOP w0.381: Q38.4 v1(109.22,50.37)
PB_RDT: length 2.6
  TOP w0.254: R631.1 107.74,57.99 107.99,57.74 107.99,57.19 107.6,56.8 U103.6
PC4_CON_PGND: length 4.4
  TOP w0.254: J3.13 v1(31.4,10.06) ; Q13.3 Q12.1 54.58,18.87 v1(54.76,18.69) ; R234.2 v1(56.5,19.28)
PC_HB: length 3.9
  TOP w0.254: U104.2 105.59,67.73 105.53,67.67 105.53,67.06 105.69,66.9 C703.1
  TOP w0.381: 104.01,66.34 105.52,66.34 C703.1
PC_HO: length 1.2
  TOP w0.254: U104.3 v1(106.09,67.38)
PC_HOG: length 1.2
  TOP w0.381: Q40.4 v1(108.71,67.26)
PC_RDT: length 2.6
  TOP w0.254: U104.6 107.09,73.69 107.48,74.08 107.48,74.63 107.23,74.88 R637.1
PL_1V8: length 79
  TOP w0.254: U101.40 98.94,82.91 99.21,82.65 v1(99.21,82.47) ; C667.1 v1(100.63,79.4) ; v1(92.76,86.46) 92.81,86.46 92.86,86.4 U101.25 ; v1(93.9,82.39) 94.44,82.94 U101.31
  TOP w0.305: v4(12.59,41.18) 12.66,41.5 JA1.D1 ; JA1.D2 12.57,42.13 12.67,42.09 v4(12.59,41.82)
  TOP w0.381: v1(93.9,82.39) 93.14,81.63 C676.1 ; C645.1 C657.1 v1(101.52,81.71) ; C778.1 v1(79.81,18.17) ; v2(77.9,91.99) 76.81,90.9 76.81,81.27 v1(76.51,80.98) C591.1 ; v4(12.59,41.18) v4(12.59,41.82) 12.49,42.15 12.49,42.08 ; C679.1 100.5,81.45 99.49,82.47 v1(99.21,82.47) ; R598.1 v1(89.33,82.47) ; R604.1 v1(89.33,84.5) ; R600.1 v1(94.15,79.4) ; 65.72,79.41 C592.1 65.24,79.89 ; v1(95.17,79.4) R603.1 R601.1 ; R592.1 R593.1 89.45,90.09 v1(89.33,90.22) ; R599.1 v1(89.33,79.68) ; v1(89.33,85.9) 89.71,86.28 R602.1 ; R597.1 v1(97.2,79.45) ; C769.1 v1(84.12,18.29) ; C677.1 91.28,88.06 91.69,87.65 91.92,87.65 92.38,87.19 92.38,86.84 v1(92.76,86.46) ; C668.1 v1(90.15,77.64)
  BOTTOM w0.178: v1(34.61,83.97) U3.12
  BOTTOM w0.191: v1(84.12,18.29) 84.39,18.02 U118.6 ; U120.6 80.08,17.9 v1(79.81,18.17)
  BOTTOM w0.203: C719.1 49.51,54.39 U109.2 ; C755.1 52.17,42.93 U115.2 ; C733.1 49.51,48.33 U111.2
  BOTTOM w0.254: v1(101.14,87.04) 100.75,87.04 100.11,86.4 U99.25 ; U101.31 94.44,82.94 v1(93.9,82.39) ; R14.1 v1(32.81,83.87) ; v1(39.83,41.77) 39.5,41.77 39.09,42.18 R446.1 ; U101.40 98.94,82.91 99.21,82.65 v1(99.21,82.47)
  BOTTOM w0.381: R569.1 v1(103.78,82.72) ; v1(103.81,89.84) R564.1 R563.1 ; v1(91.87,79.68) C678.1 C669.1 ; C656.1 102.08,88.06 101.14,87.12 v1(101.14,87.04) ; R500.1 62.8,79.79 v1(62.51,79.5) ; v1(99.21,82.47) 99.84,82.47 100.94,81.37 C646.1 ; C733.1 49.35,49.2 49.97,49.83 v1(50.07,49.83) ; C647.1 v1(94.15,79.4) ; v4(12.59,41.82) 12.59,41.83 C582.1 ; R571.1 102.47,78.14 v1(102.79,77.82) ; v1(104.39,79.95) 103.53,80.82 R570.1 ; U91.6 v1(76.51,80.98) ; R507.1 v1(68.5,80.12) ; R573.1 v1(103.83,84.5) ; C676.1 93.14,81.63 v1(93.9,82.39) 94.15,82.14 C654.1 ; v1(104.11,86.86) 103.81,87.17 R575.1 ; R572.1 99.67,80.03 100,80.03 v1(100.63,79.4) ; v1(63.45,78.53) 63.7,78.79 64.79,78.79 U92.4 ; v1(51.74,43.99) 52.01,43.72 C755.1 ; C719.1 49.35,55.18 v1(49.08,55.45) ; R574.1 R568.1 v1(97.2,79.45)
  vias: v1(37.81,81.13) v1(38.83,81.13) v1(39.84,81.13) v1(51.76,44.75) v1(52.68,45.26)
PL_1V8_FB: length 2.8
  BOTTOM w0.203: U3.10 34.11,82.45 33.94,82.27 R14.2
  BOTTOM w0.254: R14.2 R16.1
PL_2V5: length 9.6
  TOP w0.254: v1(56.27,27.26) 55.84,27.7 v2(54.79,27.7)
  TOP w0.381: C717.1 v1(56.7,41.95) ; C741.1 57.12,58.44 56.71,58.44 v1(56.66,58.39) ; C728.1 v1(56.7,50.11) ; C753.1 v1(56.63,34.48) ; C752.1 v1(56.63,33.46) ; C727.1 v1(56.7,49.1) ; C716.1 v1(56.7,40.93) ; C740.1 v1(56.63,57.71)
  BOTTOM w0.381: 55.46,28.04 R24.1 56.01,27.48 ; 57.03,27.48 C21.1
  vias: v1(56.02,25.99) v1(57.79,27.26) v1(57.79,25.99)
PL_2V5_EN: length 2.5
  BOTTOM w0.254: C829.1 63.17,29.24 R472.2 U9.5
PL_2V5_FB: length 4.4
  BOTTOM w0.254: U9.4 57.33,29.24 C21.2 R24.2 R23.1
PL_3V3: length 155.2
  TOP w0.305: JA1.B14 v4(15.19,49.48) ; JA1.B13 v4(15.19,48.84)
  TOP w0.381: C738.1 57.12,63.34 56.65,63.34 v1(56.58,63.41) ; C795.1 76.03,63.06 v1(76.14,63.17) ; C805.1 v1(71.53,41.62) ; R579.1 56.93,72.67 R580.1 v1(56.07,72.68) ; v1(103.83,88.31) 103.58,88.06 R594.1 ; C720.1 v1(56.7,47.24) ; C712.1 v1(121.54,47.73) ; C794.1 83.27,54.42 v1(83.38,54.53) ; C766.1 118.59,94.53 v1(117.97,94.53) ; C804.1 71.73,65.8 v1(71.62,65.91) ; C666.1 v1(53.33,71.04) ; v1(87.62,16.01) 88.25,16.01 C773.1 ; C710.1 123.06,37.7 v1(123.19,37.82) ; C739.1 v1(56.56,64.11) ; v1(76.14,72.12) 76.03,72 C797.1 ; C793.1 76.03,54.11 v1(76.14,54.23) ; U42.5 v1(3.41,14.94) ; U116.14 120.79,69.99 v1(120.44,69.64) ; C768.1 v1(84.97,18.3) ; C800.1 83.27,45.73 v1(83.38,45.84) ; v1(88.44,90.85) 88.57,90.98 R605.1 ; C721.1 v1(56.7,48.26) ; v1(83.38,63.48) 83.27,63.36 C796.1 ; v1(76.14,45.28) 76.03,45.17 C799.1 ; v1(83.38,72.43) 83.27,72.31 C798.1 ; v1(71.87,24.32) 71.87,26.13 71.41,26.58 70.74,26.58 69.85,27.47 69.85,28.59 69.47,28.97 67.46,28.97 67,28.51 v1(67,27.5) 67.52,26.99 R524.1 ; C729.1 v1(56.56,55.41) ; C756.1 v1(56.56,38.47) ; C730.1 v1(56.56,56.43) ; C777.1 v1(80.66,18.18) ; C757.1 v1(56.56,39.48) ; C789.1 v1(71.73,50.45) ; C803.1 v1(71.73,58.32)
  L08_PWR w0.381: 86.98,113.44 J25.P14_L3_L 86.61,114.52 ; J47.1 70.82,5.32 ; J47.1 68.98,5.32 ; J47.1 67.15,5.32 ; J47.1 68.98,8.99 ; J47.1 70.82,8.99 ; J47.1 67.15,7.15 ; J47.1 70.82,7.15 ; J47.1 67.15,8.99 ; J25.P11_L2_U 102.92,100.72 ; J25.P11_L2_U 102.02,101.02 ; J25.P11_L2_U 102.02,98.64 ; J25.P11_L2_U 101.13,100.72 ; J25.P11_L2_U 100.83,99.83 ; J25.P11_L2_U 101.13,98.93 ; J25.P11_L2_U 102.92,98.93 ; J25.P11_L2_U 103.21,99.83 ; 87.16,107.07 J25.P14_L1_U ; J25.P14_L1_U 88.94,105.28 ; J25.P14_L1_U 87.16,105.28 ; J25.P14_L1_U 88.05,107.37 ; J25.P14_L1_U 88.05,104.99 ; J25.P14_L1_U 89.24,106.18 ; J25.P14_L1_U 88.94,107.07 ; J25.P14_L1_U 86.86,106.18 ; 103.47,114.52 J25.P11_L4_L 103.1,113.44
  BOTTOM w0.178: U97.12 67.41,26.6 67.25,26.76 67.25,27.26 v1(67,27.5)
  BOTTOM w0.191: v1(86.02,16.18) 85.61,16.6 U118.10 ; v1(80.66,18.18) 80.48,18 U120.7 ; v1(84.97,18.3) 84.79,18.12 U118.7
  BOTTOM w0.203: U111.5 51.53,47.29 v1(51.61,47.37) ; U109.5 51.18,53.35 51.62,53.8 51.62,53.93 v1(51.89,54.2) ; U100.2 v1(53.33,71.04) ; v1(54.27,41.97) 54.19,41.9 U115.5 ; U111.3 49.91,48.28 C732.1 50.31,48.31 U111.4 ; U115.3 52.57,42.88 C754.1 ; C718.1 49.91,54.34 U109.3
  BOTTOM w0.254: U136.8 123.67,63 123.85,63.18 123.85,64.26 C801.1 v1(123.8,65.16) ; U129.3 75.74,58.92 75.32,58.5 v1(75.06,58.5) ; U127.3 75.74,49.97 75.32,49.55 v1(75.06,49.55) ; U128.7 83.48,54.44 v1(83.38,54.53) ; v1(76.14,63.17) 76.24,63.08 U129.7 ; v1(83.38,63.48) 83.48,63.38 U130.7 ; U134.3 82.98,41.59 82.56,41.16 v1(82.3,41.16) ; v1(82.3,49.86) 82.56,49.86 82.98,50.28 U128.3 ; v1(75.06,40.61) 75.32,40.61 75.74,41.03 U133.3 ; v1(83.38,72.43) 83.48,72.33 U132.7 ; v1(82.3,67.75) 82.56,67.75 82.98,68.17 U132.3 ; v1(82.3,58.8) 82.56,58.8 82.98,59.23 U130.3 ; U127.7 76.24,54.13 v1(76.14,54.23) ; v1(75.06,67.44) 75.32,67.44 75.74,67.87 U131.3 ; v1(76.14,72.12) 76.24,72.02 U131.7 ; v1(76.14,45.28) 76.24,45.18 U133.7 ; U134.7 83.48,45.74 v1(83.38,45.84) ; v1(3.41,14.94) 3.38,14.97 3.41,14.97 v1(3.41,14.94)
  BOTTOM w0.381: R565.1 v1(89.45,88.06) ; U117.16 v1(125.54,88.18) ; v1(119.99,45.23) 119.58,44.82 C802.1 119.17,44.24 119.5,43.92 U135.8 ; v1(56.07,69.63) 56.83,70.39 U100.8 ; U107.6 121.79,57 v1(121.66,56.87) 121.41,57.13 C714.1 ; v1(71.62,65.91) 71.73,65.8 U125.8 ; C237.1 2.62,14.94 v1(3.41,14.94) ; R166.1 v1(7.03,11.42) ; v1(104.69,91.87) 104.57,91.74 R576.1 ; U137.8 v1(71.53,41.62) ; C785.1 v1(66.58,12.07) ; U123.8 v1(71.73,50.45) ; C764.1 120.68,69.88 v1(120.44,69.64) ; C581.1 15.07,49.59 v4(15.19,49.48) ; R672.1 v1(127.26,94.17) ; U106.6 122.65,47.86 121.68,47.86 121.55,47.73 v1(121.54,47.73) ; 75.25,83.64 R471.1 74.69,83.08 ; R622.1 v1(133.91,36.76) ; U124.8 v1(71.73,58.32) ; v1(50.22,55.45) 50.13,55.35 C718.1 ; C754.1 52.79,43.9 v1(52.88,43.99) ; 62.62,28.34 R472.1 63.18,27.78 ; U119.14 88.1,15.49 v1(87.62,16.01) ; C747.1 114.72,27.23 v1(114.72,27.23) U113.6 ; C732.1 v1(50.13,49.09) ; U105.6 v1(123.19,37.82) ; U117.6 v1(117.97,94.53) ; R680.1 v1(69.02,11.96)
  vias: v1(36.14,53.16) v1(36.19,51.61) v1(36.22,49.86) v1(36.22,48.84) v1(62.24,27.39) v1(62.24,26.12) v1(63,26.76) v1(72.89,24.32) v1(73.29,83.9) v1(73.92,83.14) v1(73.9,24.32) v1(74.56,83.9) v1(108.5,87.04) v1(109.39,93.14) v1(109.39,91.87) v1(109.77,87.04) v2(70.73,23.69)
PL_3V3_FB: length 3.2
  TOP w0.381: R525.1 68.28,25.94 R524.2 67.52,25.94 v1(66.66,25.94)
  BOTTOM w0.178: v1(66.66,25.94) 66.8,25.8 U97.10
PL_4V5_TRQ: length 19
  TOP w0.381: v1(91.61,11.1) 92.05,11.53 C780.1
  L10_SIG w0.381: J45.1 90.34,8.81 ; J45.1 91.57,8.38 ; J45.1 91.57,5.93 ; J45.1 89.12,5.93 ; J45.1 92,7.15 ; J45.1 88.69,7.15 ; J45.1 90.34,5.5 ; J45.1 89.12,8.38
  BOTTOM w0.381: U119.13 90.1,14.84 v1(90.35,15.09) ; 77.52,17.08 R684.1 76.96,17.63 ; C788.1 75.94,17.63 ; R673.1 v1(83.23,12.08)
  vias: v1(75.18,19.12) v1(75.18,17.85) v1(76.7,17.85) v1(91.18,15.64) v1(92.07,15.64) v1(92.99,15.64) v2(76.88,19.1)
PL_4V5_TRQ_FB: length 4.4
  BOTTOM w0.13: R685.1 R684.2 C788.2 75.64,15.88 U122.4
PL_5V0: length 42
  TOP w0.381: U116.1 128.48,69.99 v1(128.82,69.64) ; TP14.1 130.54,77.83 v1(130.54,77.83) R666.1 ; R664.1 R665.1 v1(130.27,72.56) ; R667.1 v1(117.33,97.49)
  L10_SIG w0.381: 121.92,77.52 J43.7 ; J43.7 122.18,76.71 ; J43.7 122.98,76.45 ; J43.7 122.98,78.58 ; J43.7 122.18,78.32 ; J43.7 123.79,76.71 ; J43.7 123.79,78.32 ; J43.7 124.05,77.52 ; 122.18,80.86 J43.8 ; J43.8 124.05,80.06 ; J43.8 123.79,79.25 ; J43.8 122.98,78.99 ; J43.8 121.92,80.06 ; J43.8 122.18,79.25 ; J43.8 122.98,81.12 ; J43.8 123.79,80.86 ; J42.4 136.12,72.49 ; J42.4 133.79,73.48 ; J42.4 134.13,74.47 ; J42.4 136.12,74.47 ; J42.4 135.12,72.15 ; J42.4 134.13,72.49 ; J42.4 135.12,74.81 ; J42.4 136.46,73.48
  BOTTOM w0.381: C767.1 121.8,75.57 v1(122.09,75.87) ; C763.1 128.48,69.99 v1(128.82,69.64) ; v1(130.54,77.83) 130.54,77.83 TP14.1 ; 124.14,73.79 C618.1 123.58,74.34 ; C765.1 J42.4
  vias: v1(123.43,74.63) v1(123.5,75.67) v1(124.67,75.73) v1(124.7,74.63)
PL_12V0: length 35.5
  TOP w0.381: v1(104.8,13.38) C783.1 U121.4
  L12_SIG w0.381: v1(104.8,13.38) 104.8,13.38 104.8,15.82 104.42,16.2 103.48,16.2 102.94,16.73 102.94,19.07 101.7,20.32 83.97,20.32 81.13,23.15 v1(80,23.15)
  BOTTOM w0.381: 80,24.6 C617.1 79.21,23.63
  vias: v1(78.83,23.12) v1(80.23,24.55) v1(101.93,68.79) v1(102.44,51.9) v1(102.44,35.01) v1(103.2,68.79) v1(103.71,51.9) v1(103.71,35.01) v1(104.34,68.79) v1(104.85,51.9) v1(104.85,35.01) v2(80.31,22.02)
PL_ETH_0V9: length 17.4
  TOP w0.254: C683.1 v1(98.22,77.11) ; C684.1 91.61,83.49 91.82,83.69 91.82,84.07 ; TP9.1 v1(74.15,90.09) ; U101.4 100.36,85.4 v1(100.88,84.88) ; U101.36 96.94,82.45 v1(97.68,81.71) 98.22,81.17 C672.1 ; U101.28 93.06,84.9 92.89,84.73 v1(92.51,84.73)
  BOTTOM w0.254: U99.36 96.44,82.52 96.19,82.27 v1(96.19,81.71) C650.1 ; U99.4 93.18,85.4 v1(92.51,84.73) ; 100.86,84.9 U99.28
  BOTTOM w0.381: v1(101.52,83.96) 101.87,83.61 C673.1 ; 74.95,90.8 R27.1 74.39,90.24 ; C661.1 v1(92.04,76.84) ; 74.39,89.23 C27.1
  vias: v1(74.04,87.78) v1(74.06,88.9) v1(91.75,84.73) v1(101.56,85.87)
PL_ETH_0V9_EN: length 2.7
  BOTTOM w0.254: U8.5 R471.2 77.16,83.08 77.19,83.11 C828.1
PL_ETH_0V9_FB: length 3.8
  BOTTOM w0.254: C27.2 76.15,88.93 U8.4
  BOTTOM w0.381: R29.1 R27.2 C27.2
PL_GEM1_LED1_LS: length 16.7
  TOP w0.127: R577.2 v1(78.21,94.15)
  L03_SIG w0.102: v1(78.21,94.15) 79.24,95.19 79.24,98.95 83.93,103.64 J25.P13_L1_U
PL_GEM1_LED2_LS: length 24.3
  TOP w0.127: R578.2 v1(108.57,85.39)
  L03_SIG w0.102: v1(108.57,85.39) 108.57,85.88 108.04,86.42 108.04,95.76 105.63,98.16 105.63,102.56 J25.P12_L2_U
PL_GEM1_MDI_0_N: length 26.3
  L12_SIG w0.089: v5(95.56,90.2) 95.31,89.95 95.31,89.62 94.95,89.25 92.89,89.25 91.99,90.15 91.03,90.15 89.06,92.12 89.06,102.82 89.91,103.67 89.91,105.27 90.35,105.7 91.61,105.7 91.73,105.83 J25.P1_U
  BOTTOM w0.089: v5(95.56,90.2) 95.32,89.96 95.32,89.7 95.44,89.58 U99.13
PL_GEM1_MDI_0_P: length 26.3
  L12_SIG w0.089: v5(94.78,90.2) 95.06,89.92 95.06,89.72 94.84,89.51 92.99,89.51 92.09,90.41 91.14,90.41 90.91,90.64 90.91,90.79 91.21,91.08 91.21,91.23 91.1,91.34 90.95,91.34 90.65,91.05 90.5,91.05 89.32,92.23 89.32,102.72 90.16,103.57 90.16,105.16 90.45,105.45 91.71,105.45 91.91,105.65 J25.P2_U
  BOTTOM w0.089: U99.12 94.94,89.58 95.07,89.7 95.07,89.91 v5(94.78,90.2)
PL_GEM1_MDI_1_N: length 23.3
  L12_SIG w0.089: v5(96.56,92.32) 96.51,92.32 96.3,92.11 96.3,91.86 95.93,91.49 92.39,91.49 91.65,92.22 91.65,94.02 90.16,95.51 90.16,102.49 90.91,103.23 91.68,103.23 91.73,103.29 J25.P3_U
  BOTTOM w0.089: U99.15 96.44,89.53 96.33,89.65 96.33,90.33 96.63,90.64 96.63,91.52 96.33,91.83 96.33,92.09 v5(96.56,92.32)
PL_GEM1_MDI_1_P: length 23.3
  L12_SIG w0.089: J25.P4_U 91.91,103.11 91.78,102.98 91.01,102.98 90.42,102.38 90.42,95.61 91.91,94.12 91.91,92.33 92.49,91.74 94.8,91.74 94.9,91.85 94.9,92.27 95.01,92.38 95.16,92.38 95.27,92.27 95.27,91.85 95.38,91.74 95.82,91.74 96.04,91.96 96.04,92.11 95.83,92.32 v5(95.78,92.32)
  BOTTOM w0.089: U99.14 95.94,89.5 96.07,89.62 96.07,90.44 96.38,90.74 96.38,91.41 96.07,91.72 96.07,92.03 v5(95.78,92.32)
PL_GEM1_MDI_2_N: length 21.4
  L12_SIG w0.089: v5(97.56,90.2) 97.3,90.46 97.3,91.11 97.78,91.59 98.81,91.59 99.36,92.14 99.36,93.62 98.73,94.26 98.73,94.31 96.29,94.31 95.76,94.83 95.76,101.35 95.1,102 92.99,102 92.83,101.84 J25.P5_U
  BOTTOM w0.089: U99.17 97.44,89.58 97.32,89.7 97.32,89.96 v5(97.56,90.2)
PL_GEM1_MDI_2_P: length 21.3
  L12_SIG w0.089: v5(96.78,90.2) 97.04,90.46 97.04,91.22 97.67,91.85 98.7,91.85 99.11,92.25 99.11,93.52 98.57,94.05 96.18,94.05 95.51,94.73 95.51,100.46 95.4,100.57 95.17,100.57 95.07,100.67 95.07,100.82 95.17,100.92 95.4,100.92 95.51,101.03 95.51,101.24 95,101.75 93.1,101.75 93,101.66 J25.P6_U
  BOTTOM w0.089: U99.16 96.94,89.58 97.07,89.7 97.07,89.91 v5(96.78,90.2)
PL_GEM1_MDI_3_N: length 16.5
  L12_SIG w0.089: v5(98.56,92.32) 98.56,92.38 98.28,92.65 98.28,93.2 97.89,93.58 95.65,93.58 94.87,94.37 94.87,98.84 94.24,99.46 92.99,99.46 92.83,99.3 J25.P7_U
  BOTTOM w0.089: v5(98.56,92.32) 98.32,92.09 98.32,91.76 98.6,91.47 98.6,90.41 98.32,90.12 98.32,89.6 98.44,89.47 U99.19
PL_GEM1_MDI_3_P: length 16.5
  L12_SIG w0.089: J25.P8_U 93,99.12 93.1,99.21 94.14,99.21 94.62,98.73 94.62,98.48 94.51,98.37 94.29,98.37 94.19,98.27 94.19,98.12 94.29,98.02 94.51,98.02 94.62,97.91 94.62,94.26 95.55,93.33 97.79,93.33 98.03,93.09 98.03,92.62 97.78,92.38 v5(97.78,92.32)
  BOTTOM w0.089: v5(97.78,92.32) 98.07,92.04 98.07,91.65 98.35,91.37 98.35,90.51 98.07,90.23 98.07,89.63 97.94,89.51 U99.18
PL_GEM1_MDIX_MODE: length 3.6
  BOTTOM w0.13: U99.27 100.49,85.4 100.53,85.37 101.75,85.37 101.77,85.39 R587.1 R573.2
PL_GEM1_RESET_B: length 130.5
  L03_SIG w0.102: v1(31.21,41.22) 31.33,41.35 31.78,41.35 31.85,41.42 35.81,41.42 35.83,41.44 36.92,41.44 37.62,42.15 37.64,42.15 38.1,42.61 38.1,45.18 40.94,48.02 50.08,48.02 50.72,48.66 50.72,49.47 55.02,53.78 55.02,63.94 56.14,65.06 67.11,65.06 75.02,72.96 79.51,72.96 79.86,73.31 92.85,73.31 94.25,71.91 102.89,71.91 103.17,72.18 103.17,72.19 106.98,76 106.98,77.65 107.13,77.79 107.13,85.83 106.26,86.7 105.9,86.7 105.62,86.97 105.62,87.15 105.18,87.59 99.02,87.59 98.05,88.57 v1(92.12,88.57)
  BOTTOM w0.13: v1(31.21,41.22) 31.45,41.47 U19.12 ; R565.2 91.31,88.06 91.82,88.57 v1(92.12,88.57) 92.76,87.93 92.76,87.3 93.15,86.9 U99.7
PL_GEM2_LED3_LS: length 25.5
  TOP w0.127: R606.2 v1(78.08,96.82)
  L03_SIG w0.102: v1(78.08,96.82) 78.08,98.83 88.37,109.11 90.01,109.11 91.69,110.79 91.69,113.42 J25.P13_L3_L
PL_GEM2_LED4_LS: length 37.3
  TOP w0.127: R607.2 v1(108.57,82.72)
  L03_SIG w0.102: J25.P12_L4_L 98.25,113.28 98.25,110.09 100.51,107.83 100.51,105.96 105.15,101.32 105.15,97.96 107.55,95.56 107.55,86.14 107.77,85.92 107.77,83.53 v1(108.57,82.72)
PL_GEM2_MDI_0_N: length 24.8
  TOP w0.089: v3(97.78,90.2) 98.07,89.91 98.07,89.63 97.94,89.51 U101.13
  L03_SIG w0.089: v3(97.78,90.2) 97.91,90.2 98.04,90.07 98.04,89.66 98.4,89.3 100.81,89.3 101.72,90.21 101.72,93.37 100.76,94.33 100.76,104.03 99.06,105.74 98.44,105.74 98.34,105.83 J25.P1_L
PL_GEM2_MDI_0_P: length 24.8
  TOP w0.089: U101.12 98.44,89.47 98.32,89.6 98.32,89.96 v3(98.56,90.2)
  L03_SIG w0.089: v3(98.56,90.2) 98.42,90.2 98.3,90.07 98.3,89.77 98.51,89.56 100.71,89.56 101.46,90.31 101.46,91.24 101.36,91.34 100.91,91.34 100.8,91.45 100.8,91.6 100.91,91.71 101.36,91.71 101.46,91.82 101.46,93.27 100.51,94.22 100.51,103.93 98.95,105.48 98.33,105.48 98.17,105.65 J25.P2_L
PL_GEM2_MDI_1_N: length 20.1
  TOP w0.089: v3(96.78,92.32) 97.07,92.04 97.07,89.7 96.94,89.58 U101.15
  L03_SIG w0.089: J25.P3_L 98.34,103.29 98.46,103.17 99.41,103.17 99.86,102.72 99.86,93.7 98.45,92.29 98.45,91.99 97.93,91.47 97.34,91.47 97.04,91.77 97.04,92.06 v3(96.78,92.32)
PL_GEM2_MDI_1_P: length 20.1
  TOP w0.089: U101.14 97.44,89.58 97.32,89.7 97.32,92.09 v3(97.56,92.32)
  L03_SIG w0.089: v3(97.56,92.32) 97.3,92.06 97.3,91.87 97.45,91.72 97.83,91.72 98.2,92.1 98.2,92.4 98.75,92.95 98.75,93.1 98.43,93.41 98.43,93.57 98.54,93.67 98.69,93.67 99.01,93.36 99.16,93.36 99.61,93.81 99.61,102.62 99.31,102.92 98.36,102.92 98.17,103.11 J25.P4_L
PL_GEM2_MDI_2_N: length 20.3
  TOP w0.089: v3(95.78,90.2) 96.07,89.91 96.07,89.63 95.94,89.51 U101.17
  L03_SIG w0.089: J25.P5_L 97.25,101.84 97.09,102 95.28,102 94.42,101.14 94.42,94.98 93.14,93.7 93.14,91.73 93.44,91.42 96.06,91.42 96.33,91.15 96.33,90.66 95.87,90.2 v3(95.78,90.2)
PL_GEM2_MDI_2_P: length 20.3
  TOP w0.089: v3(96.56,90.2) 96.32,89.96 96.32,89.66 96.44,89.53 U101.16
  L03_SIG w0.089: v3(96.56,90.2) 96.56,90.53 96.59,90.55 96.59,91.26 96.17,91.68 93.55,91.68 93.39,91.83 93.39,93.59 93.6,93.8 93.75,93.8 94.01,93.53 94.17,93.53 94.27,93.64 94.27,93.79 94.01,94.06 94.01,94.21 94.67,94.87 94.67,101.03 95.39,101.75 96.98,101.75 97.07,101.66 J25.P6_L
PL_GEM2_MDI_3_N: length 13.5
  TOP w0.089: v3(94.78,92.32) 95.07,92.04 95.07,89.7 94.94,89.58 U101.19
  L03_SIG w0.089: v3(94.78,92.32) 95.04,92.59 95.04,94.19 95.35,94.5 95.35,98.73 96.09,99.46 97.09,99.46 97.25,99.3 J25.P7_L
PL_GEM2_MDI_3_P: length 13.5
  TOP w0.089: v3(95.56,92.32) 95.32,92.09 95.32,89.7 95.44,89.58 U101.18
  L03_SIG w0.089: v3(95.56,92.32) 95.3,92.59 95.3,93.16 95.4,93.27 95.64,93.27 95.75,93.37 95.75,93.53 95.64,93.63 95.4,93.63 95.3,93.74 95.3,94.09 95.6,94.39 95.6,98.62 96.19,99.21 96.98,99.21 97.07,99.12 J25.P8_L
PL_GEM2_MDIX_MODE: length 3.8
  TOP w0.127: R604.2 R613.1 91.49,85.39 91.61,85.26 92.12,85.26 92.26,85.4 U101.27
PL_GEM2_RESET_B: length 119.5
  TOP w0.127: R594.2 101.45,88.06 100.3,86.9 U101.7
  TOP w0.13: R594.2 102.85,87.42 104.59,87.42 v1(105.1,86.91)
  L03_SIG w0.102: v1(30.23,41.28) 30.78,41.83 31.58,41.83 31.68,41.93 35.64,41.93 36.34,42.63 36.91,42.63 37.46,43.18 37.46,45.21 40.85,48.6 48.82,48.6 49.3,49.09 49.3,50.01 49.96,50.67 51.05,50.67 54.54,54.16 54.54,64.14 55.94,65.54 66.91,65.54 74.82,73.45 75.22,73.45 79.31,73.45 79.66,73.79 93.51,73.79 94.33,72.97 103.27,72.97 104.78,74.49 104.78,77.35 106.64,79.22 106.64,85.63 106.05,86.22 105.39,86.22 105.1,86.51 v1(105.1,86.91)
  BOTTOM w0.13: U19.13 31.75,41.87 31.68,41.8 30.74,41.8 v1(30.23,41.28)
PMOD1_IO1_HDA11: length 56.3
  TOP w0.13: R274.2 C372.1 v1(24.87,15.03) 24.9,15 J2.1
  L10_SIG w0.102: v1(24.87,15.03) 25.45,15.61 25.45,19.57 24.51,20.51 24.51,20.77 25.11,21.36 25.11,21.62 24.93,21.8 24.68,21.8 24.08,21.2 23.83,21.2 23.65,21.38 23.65,21.63 24.25,22.23 24.25,22.48 24.07,22.66 23.82,22.66 23.22,22.06 22.97,22.06 22.79,22.24 22.79,22.49 23.39,23.09 23.39,23.34 23.21,23.52 22.95,23.52 22.36,22.92 22.1,22.92 21.92,23.1 21.92,23.35 22.52,23.95 22.52,24.2 22.34,24.38 22.09,24.38 21.49,23.78 21.24,23.78 21.06,23.96 21.06,24.21 21.66,24.81 21.66,25.07 21.48,25.24 21.23,25.24 20.63,24.65 20.38,24.65 19.55,25.47 19.55,32.82 11.65,40.72 11.65,47.75 9.44,49.96 v1(9.44,50.08)
  BOTTOM w0.13: R276.2 v1(9.44,50.08)
PMOD1_IO2_HDA12: length 59.7
  TOP w0.13: C374.1 v1(22.33,15.03) 22.36,15 J2.3
  L10_SIG w0.102: v1(9.44,52.24) 8.4,52.24 7.83,51.67 7.83,49.43 8.91,48.36 9.55,48.36 10.45,47.46 10.45,37.12 8.96,35.63 8.96,30.72 12.12,27.55 12.6,27.55 12.75,27.7 12.75,28.09 12.9,28.24 13.11,28.24 13.25,28.09 13.25,27.7 13.4,27.55 13.61,27.55 13.76,27.7 13.76,28.09 13.91,28.24 14.12,28.24 14.27,28.09 14.27,27.7 14.42,27.55 15.43,27.55 16.22,26.76 16.22,25.13 16.62,24.72 16.83,24.72 17.17,25.06 17.38,25.06 17.53,24.91 17.53,24.7 17.19,24.36 17.19,24.15 17.34,24.01 17.55,24.01 17.89,24.34 18.1,24.34 18.25,24.19 18.25,23.98 17.91,23.65 17.91,23.44 18.06,23.29 18.27,23.29 18.6,23.62 18.82,23.62 18.96,23.47 18.96,23.26 18.63,22.93 18.63,22.72 18.97,22.38 19.22,22.38 19.4,22.57 19.66,22.57 19.83,22.39 19.83,22.14 19.65,21.95 19.65,21.7 19.83,21.52 20.08,21.52 20.26,21.71 20.52,21.71 20.7,21.53 20.7,21.27 20.51,21.09 20.51,20.84 20.69,20.66 20.94,20.66 21.13,20.84 21.38,20.84 21.56,20.66 21.56,20.41 21.37,20.23 21.37,19.97 21.64,19.71 21.64,15.73 v1(22.33,15.03)
  BOTTOM w0.13: R278.2 v1(9.44,52.24)
PMOD1_IO3_HDA13: length 59
  TOP w0.13: J2.5 19.82,14.88 v1(19.66,15.03) C377.1
  L10_SIG w0.102: v1(19.66,15.03) 19.18,15.52 19.18,18.12 18.71,18.58 15.89,18.58 14.96,19.52 14.96,19.77 15.2,20.01 15.2,20.26 15.02,20.44 14.77,20.44 14.53,20.2 14.27,20.2 14.1,20.38 14.1,20.63 14.34,20.87 14.34,21.13 14.16,21.31 13.91,21.31 13.66,21.06 13.41,21.06 12.69,21.79 12.69,22.88 12.84,23.03 13.56,23.03 13.71,23.18 13.71,23.39 13.56,23.53 12.84,23.53 12.69,23.68 12.69,23.89 12.84,24.04 13.56,24.04 13.71,24.19 13.71,24.4 13.56,24.55 12.84,24.55 12.69,24.7 12.69,25.1 7.68,30.11 7.68,36.37 8.07,36.75 8.07,40.15 8.36,40.44 8.36,46.88 6.03,49.21 6.03,51.36 6.87,52.2 6.87,53.38 8.15,54.67 8.57,54.67 v1(9.44,55.55)
  BOTTOM w0.13: R280.2 v1(9.44,55.55)
